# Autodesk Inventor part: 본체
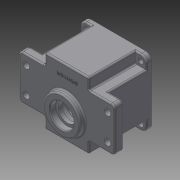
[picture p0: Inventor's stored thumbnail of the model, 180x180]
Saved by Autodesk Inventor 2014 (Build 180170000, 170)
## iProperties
Created: 2015-07
Part Number: 본체
Material: Generic
Document SubType Name: Modeling
Designer: Administrator
Density: 1 g/cm^3
Appearance: Default
Author: Administrator
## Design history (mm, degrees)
sketch "스케치1"
  geometry: L1 (-65, -30)-(65, -30); L2 (65, -30)-(65, 30); L3 (65, 30)-(-65, 30); L4 (-65, 30)-(-65, -30); L5 (-65, -30)-(65, 30); L6 (65, -30)-(-65, 30); 1 further point
  constraints: 12 end point, 2 midpoint, 2 parallel, 1 horizontal, 1 perpendicular
  dimensions: "d0" = 130 distance of L3.end L2.end; "d1" = 60 distance of L2.end L1.end
extrude "돌출1" new body sketch "스케치1" distance "d2" = 12; taper "d3" = 0 deg
sketch "스케치2"
  geometry: L1 (45, -45)-(-45, -45); L2 (-45, -45)-(-45, 45); L3 (-45, 45)-(45, 45); L4 (45, 45)-(45, -45); L5 (45, -45)-(-45, 45); L6 (-45, -45)-(45, 45); 1 further point
  constraints: 12 end point, 2 midpoint, 2 parallel, 1 horizontal, 1 perpendicular
  dimensions: "d4" = 90 distance of L2.end L3.end; "d5" = 90 distance of L1.end L2.end
extrude "돌출2" join sketch "스케치2" distance "d6" = 70; taper "d7" = 0 deg
fillet "모깎기1" dims "d8" = 5
sketch "스케치4"
  geometry: C1 r 4.5 at (-55, 17.5); C2 r 4.5 at (-55, -17.5); C3 r 4.5 at (55, 17.5); C4 r 4.5 at (55, -17.5); 1 further point
  constraints: 4 centre point, 2 vertical alignment, 1 horizontal alignment
  dimensions: "d9" = 9 diameter of C1; "d10" = 9 diameter of C2; "d11" = 9 diameter of C3; "d12" = 9 diameter of C4; "d13" = 55 horizontal distance of point (0, 0) C1.centre; "d14" = 55 horizontal distance of C3.centre point (0, 0); "d15" = 35 distance of C3.centre C4.centre; "d16" = 35 distance of C1.centre C2.centre; "d17" = 17.5 vertical distance of point (0, 0) C4.centre
extrude "돌출3" cut sketch "스케치4" distance "d18" = 70; taper "d19" = 0 deg
sketch "스케치5"
  geometry: L1 (45, 45)-(45, 30) reference; L2 (-30, -45)-(-30, -30); L3 (-30, 45)-(30, 45); L4 (30, 45)-(30, 30); L5 (30, -45)-(-30, 45); L6 (-30, -45)-(30, 45); L7 (-45, 30)-(-30, 30); L8 (30, 30)-(45, 30); L9 (45, -30)-(30, -30); L10 (-45, -30)-(-30, -30); L11 (-45, 30)-(-45, 45); L12 (-30, 45)-(-45, 45); L13 (30, 45)-(45, 45); L14 (45, 30)-(45, 45); L15 (45, -30)-(45, -45); L16 (45, -45)-(30, -45); L17 (-45, -30)-(-45, -45); L18 (-45, -45)-(-30, -45); L19 (-30, 30)-(-30, 45); L20 (30, 30)-(30, -30); L21 (30, -30)-(30, -45); L22 (-30, -30)-(-30, 30); 1 further point
  constraints: 42 end point, 10 perpendicular, 9 parallel, 3 collinear, 2 midpoint, 1 point on line
  dimensions: "d20" = 60 distance of L3.start L3.end; "d21" = 90 distance of L2.start L3.start; "d22" = 60 distance between parallel lines of L4 L2; "d23" = 90 deg angle of L21 L18
extrude "돌출4" cut sketch "스케치5" distance "d24" = 63; taper "d25" = 0 deg
fillet "모깎기2" dims "d26" = 8
sketch "스케치6"
  geometry: L1 (30, 45)-(37, 45) reference; L2 (30, 30)-(30, 45) reference; L3 (45, 30)-(30, 30) reference; L4 (45, 37)-(45, 30) reference; L5 (45, -30)-(45, -37) reference; L6 (30, -30)-(45, -30) reference; L7 (30, -45)-(30, -30) reference; L8 (37, -45)-(30, -45) reference; L9 (-30, -45)-(-37, -45) reference; L10 (-30, -30)-(-30, -45) reference; L11 (-45, -30)-(-30, -30) reference; L12 (-45, -37)-(-45, -30) reference; C1 r 3.5 at (-37, -37); C2 r 3.5 at (37, -37); C3 r 3.5 at (-37, 37); C4 r 3.5 at (37, 37); A1 r 8 centre (-37, 37) between (-37, 45) and (-45, 37) reference; A2 r 8 centre (37, 37) between (45, 37) and (37, 45) reference; A3 r 8 centre (37, -37) between (37, -45) and (45, -37) reference; A4 r 8 centre (-37, -37) between (-45, -37) and (-37, -45) reference; 1 further point
  constraints: 4 centre point, 4 coincident
  dimensions: "d27" = 7 diameter of C1; "d28" = 7 diameter of C2; "d29" = 7 diameter of C3; "d30" = 7 diameter of C4
extrude "돌출5" cut sketch "스케치6" stored distance "d31" = 63; taper "d32" = 0 deg
sketch "스케치7"
  geometry: C1 r 40 at (0, 0); 1 further point
  constraints: 1 centre point, 1 coincident
  dimensions: "d33" = 80 diameter of C1
extrude "돌출6" cut sketch "스케치7" distance "d34" = 9; taper "d35" = 0 deg
sketch "스케치9"
  geometry: C1 r 40 at (0, 0) reference; C2 r 39 at (0, 0)
  constraints: 1 centre point, 1 coincident
  dimensions: "d36" = 78 diameter of C2
extrude "돌출7" cut sketch "스케치9" distance "d37" = 52; taper "d38" = 0 deg
sketch "스케치10"
  geometry: L1 (0, 0)-(39, 0); L2 (0, 0)-(27.577, 27.577); A1 r 39 centre (0, 0) between (39, 0) and (27.577, 27.577) reference; A2 r 35 centre (0, 0) between (24.749, 24.749) and (21.762, 27.412); A3 r 4 centre (24.749, 24.749) between (21.809, 27.462) and (27.462, 21.809); A4 r 3.5 centre (19.238, 29.836) between (21.762, 27.412) and (21.809, 27.462); A5 r 3.5 centre (29.836, 19.238) between (32.777, 21.134) and (27.462, 21.809); A6 r 39 centre (0, 0) between (32.777, 21.134) and (27.577, 27.577); A7 r 3.5 centre (19.238, 29.836) between (15.988, 31.135) and (21.134, 32.777); A8 r 3.5 centre (29.836, 19.238) between (32.777, 21.134) and (31.135, 15.988); A9 r 3.5 centre (19.238, 29.836) between (21.809, 27.462) and (21.134, 32.777); A10 r 3.5 centre (29.836, 19.238) between (27.462, 21.809) and (27.412, 21.762); A11 r 39 centre (0, 0) between (27.577, 27.577) and (21.134, 32.777); A12 r 3.5 centre (29.836, 19.238) between (31.135, 15.988) and (32.777, 21.134); A13 r 3.5 centre (19.238, 29.836) between (21.134, 32.777) and (15.988, 31.135)
  constraints: 33 point on circle, 12 centre point, 4 coincident, 4 end point, 4 tangent, 1 horizontal, 1 point on line
  dimensions: "d39" = 45 deg angle of L1 L2; "d40" = 70 diameter of A2; "d41" = 8 diameter of A3; "d42" = 7 diameter of A4; "d43" = 7 diameter of A5
sketch "스케치11"
  geometry: C1 r 25 at (0, -11); 1 further point
  constraints: 1 centre point, 1 vertical alignment
  dimensions: "d44" = 50 diameter of C1; "d45" = 11 distance of point (0, 0) C1.centre
extrude "돌출8" join sketch "스케치11" distance "d46" = 7; taper "d47" = 0 deg
sketch "스케치12"
  geometry: C1 r 25 at (0, 0) reference; C2 r 16 at (0, 0); 1 further point
  constraints: 1 centre point, 1 coincident
  dimensions: "d48" = 32 diameter of C2
extrude "돌출9" cut sketch "스케치12" distance "d49" = 8; taper "d50" = 0 deg
sketch "스케치14"
  geometry: C1 r 39 at (0, 0) reference; C2 r 20.5 at (0, 11)
  constraints: 1 centre point, 1 vertical alignment
  dimensions: "d51" = 41 diameter of C2; "d52" = 11 distance of C1.centre C2.centre
extrude "돌출10" join sketch "스케치14" distance "d53" = 7; taper "d54" = 0 deg
sketch "스케치15"
  geometry: C1 r 20.5 at (0, 0) reference; C2 r 17.5 at (0, 0); 1 further point
  constraints: 1 centre point, 1 coincident
  dimensions: "d55" = 35 diameter of C2
extrude "돌출11" cut sketch "스케치15" distance "d56" = 10; taper "d57" = 0 deg
sketch "스케치16"
  geometry: C1 r 16 at (0, 0) reference; C2 r 12.5 at (0, 0); 1 further point
  constraints: 1 centre point, 1 coincident
  dimensions: "d58" = 25 diameter of C2
extrude "돌출12" cut sketch "스케치16" distance "d59" = 5; taper "d60" = 0 deg
sketch "스케치17"
  geometry: C1 r 39 at (0, 0) reference; C2 r 14 at (0, -20)
  constraints: 1 centre point, 1 vertical alignment
  dimensions: "d61" = 28 diameter of C2; "d62" = 20 distance of C2.centre C1.centre
extrude "돌출13" join sketch "스케치17" stored distance "d63" = 5; taper "d64" = 0 deg
sketch "스케치18"
  geometry: C1 r 11 at (0, -20); A1 r 14 centre (0, -20) between (-7.402, -8.117) and (7.402, -8.117) reference; 1 further point
  constraints: 1 centre point, 1 coincident
  dimensions: "d65" = 22 diameter of C1
extrude "돌출14" cut sketch "스케치18" distance "d66" = 7; taper "d67" = 0 deg
sketch "스케치19"
  geometry: C1 r 11 at (0, 0) reference; C2 r 9.5 at (0, 0); 1 further point
  constraints: 1 centre point, 1 coincident
  dimensions: "d68" = 19 diameter of C2
extrude "돌출15" cut sketch "스케치19" distance "d69" = 1; taper "d70" = 0 deg
extrude "돌출16" join sketch "스케치10" stored distance "d71" = 1; taper "d72" = 0 deg
sketch "스케치20"
  geometry: A1 r 4 centre (24.749, -24.749) between (27.462, -21.809) and (21.809, -27.462) reference; A2 r 4 centre (-24.749, -24.749) between (-21.809, -27.462) and (-27.462, -21.809) reference; A3 r 4 centre (-24.749, 24.749) between (-27.462, 21.809) and (-21.809, 27.462) reference; A4 r 4 centre (24.749, 24.749) between (21.809, 27.462) and (27.462, 21.809) reference; 4 further points
  constraints: 4 coincident
hole "구멍1" sketch "스케치20" at (-24.749, 24.749), (-24.749, -24.749), (24.749, -24.749), (24.749, 24.749) diameter "d73" = 3.459; stored, may be unused: countersink angle "d77" = 90 deg, drill point angle "d79" = 118 deg; dims "d74" = 12, "d75" = 4, "d76" = 2, "d78" = 15
sketch "스케치21"
  geometry: L1 (-30, 45)-(30, 45) reference; 2 further points
  constraints: 1 other
  dimensions: "d80" = 15 distance from line of L1 point (1.125, 30)
feature "엠보싱1" sketch "스케치21" dims "d8" = 5, "d81" = 0.5, "d82" = 0
chamfer "모따기1" distance "d83" = 1; stored, may be unused: second distance "d84" = 2, angle "d85" = 45 deg
fillet "모깎기3" dims "d86" = 3
fillet "모깎기4" dims "d87" = 2
fillet "모깎기5" dims "d88" = 2
fillet "모깎기6" dims "d89" = 2
fillet "모깎기7" dims "d90" = 2
fillet "모깎기8" dims "d91" = 0.3
chamfer "모따기2" distance "d92" = 1; stored, may be unused: second distance "d93" = 2, angle "d94" = 45 deg
fillet "모깎기9" dims "d95" = 2
node "솔리드1"
mirror "대칭1"
mirror "대칭2"
node "투영된 루프1"
node "투영된 루프2"
node "투영된 루프3"
node "작업 평면1"
node "작업 평면2"
node "작업 평면3"
